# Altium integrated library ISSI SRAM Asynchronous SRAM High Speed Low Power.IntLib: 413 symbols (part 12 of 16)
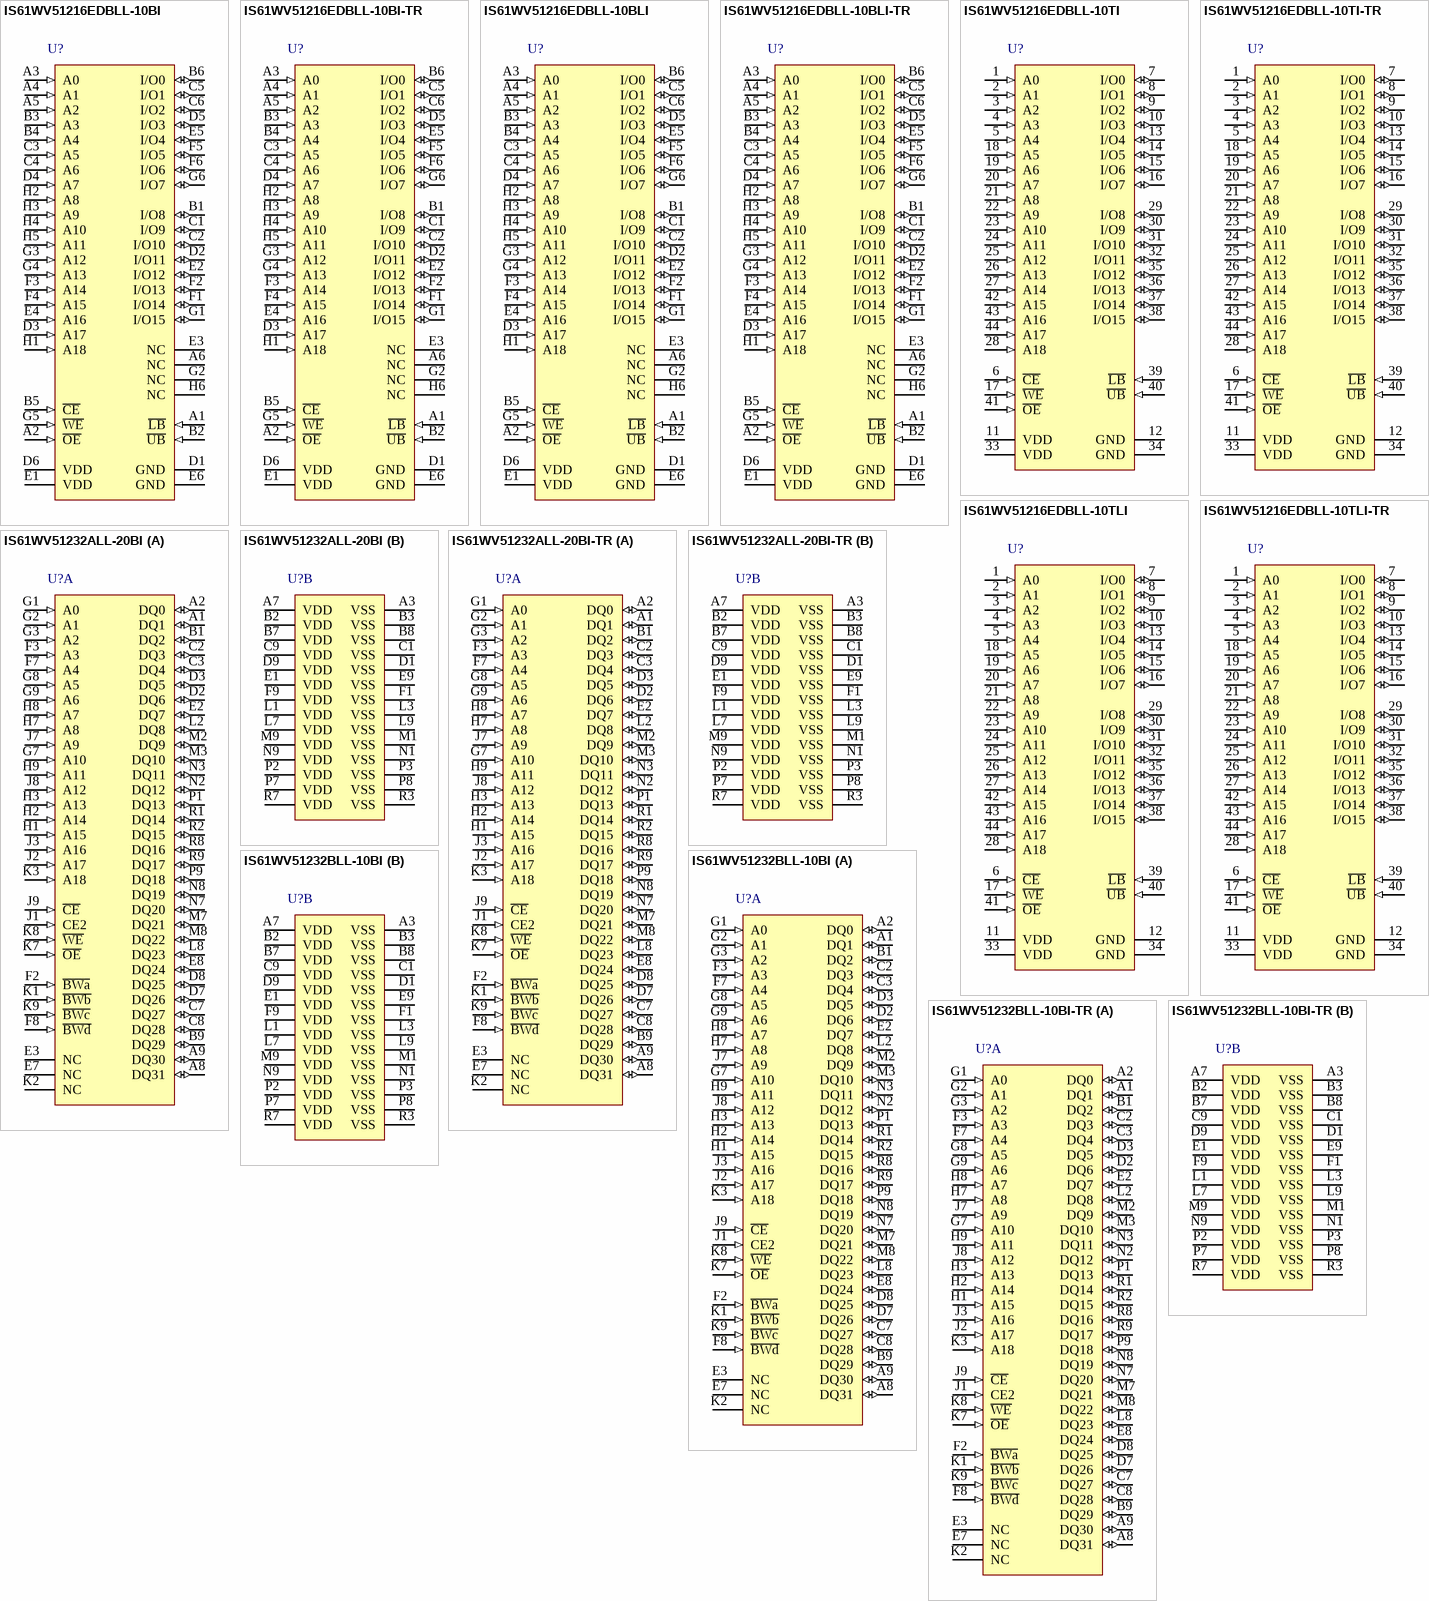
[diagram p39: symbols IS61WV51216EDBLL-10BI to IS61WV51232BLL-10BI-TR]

## IS61WV51232BLL-10BI
designator U?
16 M High Speed Asynchronous CMOS SRAM with 3.3 V Supply, 512 K x 32, -40 to 85 degC, 90-Pin BGA (LF-BGA-90); Manufacturer: Integrated Silicon Solution Inc (ISSI); PartNumber: IS61WV51232BLL-10BI; Density: 16M; Packing: Tray / Tube; Speed (ns): 10
footprint ISSI-TF-BGA-90-8000X13000DE (BGA, 90-Balls, Body 13x8mm, Pitch 0.8mm)
part A pins: A1 DQ1 (io) "Data I/O", A2 DQ0 (io) "Data I/O", A8 DQ31 (io) "Data I/O", A9 DQ30 (io) "Data I/O", B1 DQ2 (io) "Data I/O", B9 DQ29 (io) "Data I/O", C2 DQ3 (io) "Data I/O", C3 DQ4 (io) "Data I/O", C7 DQ27 (io) "Data I/O", C8 DQ28 (io) "Data I/O", D2 DQ6 (io) "Data I/O", D3 DQ5 (io) "Data I/O", D7 DQ26 (io) "Data I/O", D8 DQ25 (io) "Data I/O", E2 DQ7 (io) "Data I/O", E3 NC "No Connection", E7 NC "No Connection", E8 DQ24 (io) "Data I/O", F2 ~{BWa} (in) "Byte Write Control", F3 A3 (in) "Address Inputs", F7 A4 (in) "Address Inputs", F8 ~{BWd} (in) "Byte Write Control", G1 A0 (in) "Address Inputs", G2 A1 (in) "Address Inputs", G3 A2 (in) "Address Inputs", G7 A10 (in) "Address Inputs", G8 A5 (in) "Address Inputs", G9 A6 (in) "Address Inputs", H1 A15 (in) "Address Inputs", H2 A14 (in) "Address Inputs", H3 A13 (in) "Address Inputs", H7 A8 (in) "Address Inputs", H8 A7 (in) "Address Inputs", H9 A11 (in) "Address Inputs", J1 CE2 (in) "Chip Enable Input", J2 A17 (in) "Address Inputs", J3 A16 (in) "Address Inputs", J7 A9 (in) "Address Inputs", J8 A12 (in) "Address Inputs", J9 ~{CE} (in) "Chip Enable Input", K1 ~{BWb} (in) "Byte Write Control", K2 NC "No Connection", K3 A18 (in) "Address Inputs", K7 ~{OE} (in) "Output Enable Input", K8 ~{WE} (in) "Write Enable Input", K9 ~{BWc} (in) "Byte Write Control", L2 DQ8 (io) "Data I/O", L8 DQ23 (io) "Data I/O", M2 DQ9 (io) "Data I/O", M3 DQ10 (io) "Data I/O", M7 DQ21 (io) "Data I/O", M8 DQ22 (io) "Data I/O", N2 DQ12 (io) "Data I/O", N3 DQ11 (io) "Data I/O", N7 DQ20 (io) "Data I/O", N8 DQ19 (io) "Data I/O", P1 DQ13 (io) "Data I/O", P9 DQ18 (io) "Data I/O", R1 DQ14 (io) "Data I/O", R2 DQ15 (io) "Data I/O", R8 DQ16 (io) "Data I/O", R9 DQ17 (io) "Data I/O"
part B pins: A3 VSS (power) "Ground", A7 VDD (power) "Power", B2 VDD (power) "Power", B3 VSS (power) "Ground", B7 VDD (power) "Power", B8 VSS (power) "Ground", C1 VSS (power) "Ground", C9 VDD (power) "Power", D1 VSS (power) "Ground", D9 VDD (power) "Power", E1 VDD (power) "Power", E9 VSS (power) "Ground", F1 VSS (power) "Ground", F9 VDD (power) "Power", L1 VDD (power) "Power", L3 VSS (power) "Ground", L7 VDD (power) "Power", L9 VSS (power) "Ground", M1 VSS (power) "Ground", M9 VDD (power) "Power", N1 VSS (power) "Ground", N9 VDD (power) "Power", P2 VDD (power) "Power", P3 VSS (power) "Ground", P7 VDD (power) "Power", P8 VSS (power) "Ground", R3 VSS (power) "Ground", R7 VDD (power) "Power"

## IS61WV51232BLL-10BI-TR
designator U?
16 M High Speed Asynchronous CMOS SRAM with 3.3 V Supply, 512 K x 32, -40 to 85 degC, 90-Pin BGA (LF-BGA-90); Manufacturer: Integrated Silicon Solution Inc (ISSI); PartNumber: IS61WV51232BLL-10BI-TR; Density: 16M; Packing: Tape & Reel; Speed (ns): 10
footprint ISSI-TF-BGA-90-8000X13000DE (BGA, 90-Balls, Body 13x8mm, Pitch 0.8mm)
part A pins: A1 DQ1 (io) "Data I/O", A2 DQ0 (io) "Data I/O", A8 DQ31 (io) "Data I/O", A9 DQ30 (io) "Data I/O", B1 DQ2 (io) "Data I/O", B9 DQ29 (io) "Data I/O", C2 DQ3 (io) "Data I/O", C3 DQ4 (io) "Data I/O", C7 DQ27 (io) "Data I/O", C8 DQ28 (io) "Data I/O", D2 DQ6 (io) "Data I/O", D3 DQ5 (io) "Data I/O", D7 DQ26 (io) "Data I/O", D8 DQ25 (io) "Data I/O", E2 DQ7 (io) "Data I/O", E3 NC "No Connection", E7 NC "No Connection", E8 DQ24 (io) "Data I/O", F2 ~{BWa} (in) "Byte Write Control", F3 A3 (in) "Address Inputs", F7 A4 (in) "Address Inputs", F8 ~{BWd} (in) "Byte Write Control", G1 A0 (in) "Address Inputs", G2 A1 (in) "Address Inputs", G3 A2 (in) "Address Inputs", G7 A10 (in) "Address Inputs", G8 A5 (in) "Address Inputs", G9 A6 (in) "Address Inputs", H1 A15 (in) "Address Inputs", H2 A14 (in) "Address Inputs", H3 A13 (in) "Address Inputs", H7 A8 (in) "Address Inputs", H8 A7 (in) "Address Inputs", H9 A11 (in) "Address Inputs", J1 CE2 (in) "Chip Enable Input", J2 A17 (in) "Address Inputs", J3 A16 (in) "Address Inputs", J7 A9 (in) "Address Inputs", J8 A12 (in) "Address Inputs", J9 ~{CE} (in) "Chip Enable Input", K1 ~{BWb} (in) "Byte Write Control", K2 NC "No Connection", K3 A18 (in) "Address Inputs", K7 ~{OE} (in) "Output Enable Input", K8 ~{WE} (in) "Write Enable Input", K9 ~{BWc} (in) "Byte Write Control", L2 DQ8 (io) "Data I/O", L8 DQ23 (io) "Data I/O", M2 DQ9 (io) "Data I/O", M3 DQ10 (io) "Data I/O", M7 DQ21 (io) "Data I/O", M8 DQ22 (io) "Data I/O", N2 DQ12 (io) "Data I/O", N3 DQ11 (io) "Data I/O", N7 DQ20 (io) "Data I/O", N8 DQ19 (io) "Data I/O", P1 DQ13 (io) "Data I/O", P9 DQ18 (io) "Data I/O", R1 DQ14 (io) "Data I/O", R2 DQ15 (io) "Data I/O", R8 DQ16 (io) "Data I/O", R9 DQ17 (io) "Data I/O"
part B pins: A3 VSS (power) "Ground", A7 VDD (power) "Power", B2 VDD (power) "Power", B3 VSS (power) "Ground", B7 VDD (power) "Power", B8 VSS (power) "Ground", C1 VSS (power) "Ground", C9 VDD (power) "Power", D1 VSS (power) "Ground", D9 VDD (power) "Power", E1 VDD (power) "Power", E9 VSS (power) "Ground", F1 VSS (power) "Ground", F9 VDD (power) "Power", L1 VDD (power) "Power", L3 VSS (power) "Ground", L7 VDD (power) "Power", L9 VSS (power) "Ground", M1 VSS (power) "Ground", M9 VDD (power) "Power", N1 VSS (power) "Ground", N9 VDD (power) "Power", P2 VDD (power) "Power", P3 VSS (power) "Ground", P7 VDD (power) "Power", P8 VSS (power) "Ground", R3 VSS (power) "Ground", R7 VDD (power) "Power"

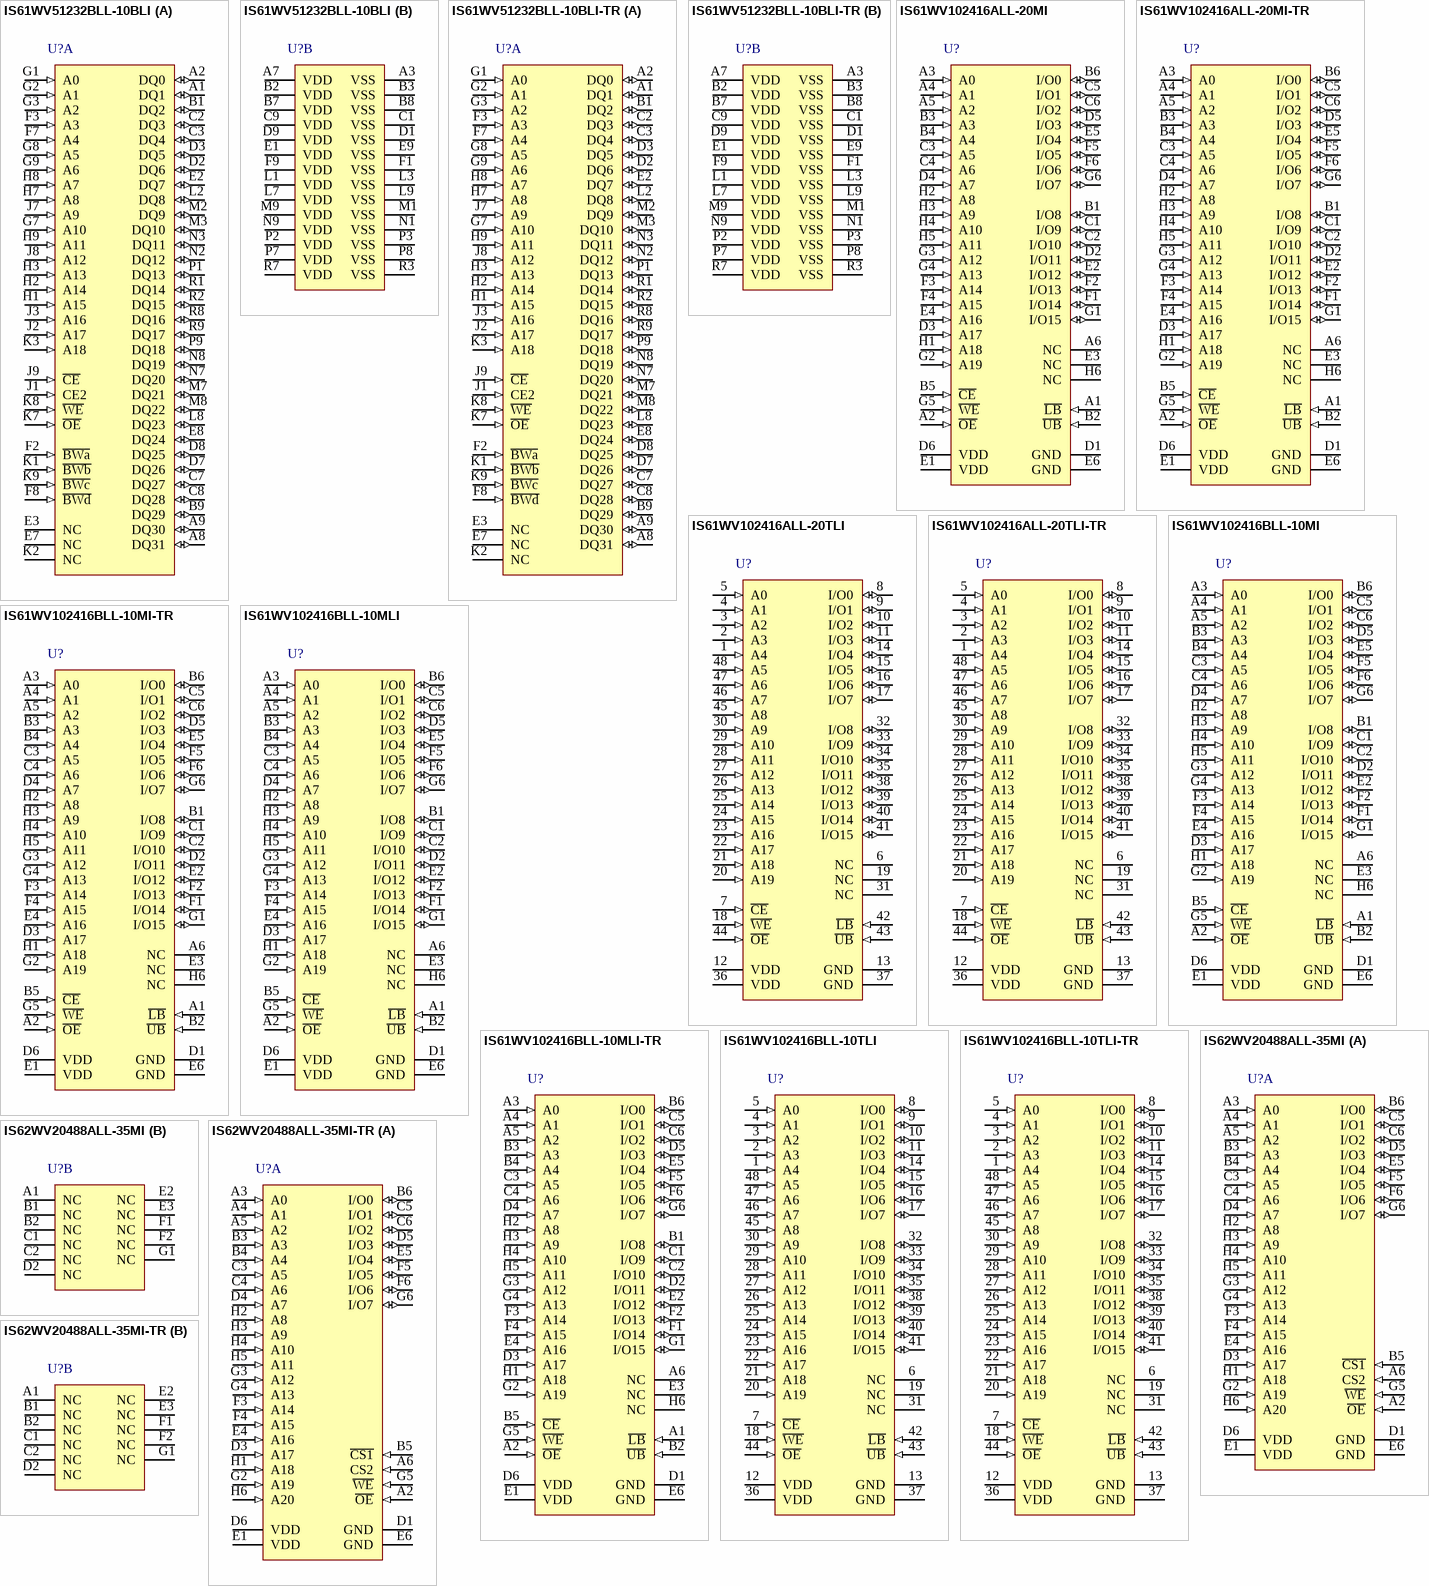
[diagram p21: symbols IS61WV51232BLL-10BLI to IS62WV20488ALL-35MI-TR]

## IS61WV51232BLL-10BLI
designator U?
16 M High Speed Asynchronous CMOS SRAM with 3.3 V Supply, 512 K x 32, -40 to 85 degC, 90-Pin BGA (LF-BGA-90), Pb-Free; Manufacturer: Integrated Silicon Solution Inc (ISSI); PartNumber: IS61WV51232BLL-10BLI; Density: 16M; Packing: Tray / Tube; Speed (ns): 10
footprint ISSI-TF-BGA-90-8000X13000DE (BGA, 90-Balls, Body 13x8mm, Pitch 0.8mm)
part A pins: A1 DQ1 (io) "Data I/O", A2 DQ0 (io) "Data I/O", A8 DQ31 (io) "Data I/O", A9 DQ30 (io) "Data I/O", B1 DQ2 (io) "Data I/O", B9 DQ29 (io) "Data I/O", C2 DQ3 (io) "Data I/O", C3 DQ4 (io) "Data I/O", C7 DQ27 (io) "Data I/O", C8 DQ28 (io) "Data I/O", D2 DQ6 (io) "Data I/O", D3 DQ5 (io) "Data I/O", D7 DQ26 (io) "Data I/O", D8 DQ25 (io) "Data I/O", E2 DQ7 (io) "Data I/O", E3 NC "No Connection", E7 NC "No Connection", E8 DQ24 (io) "Data I/O", F2 ~{BWa} (in) "Byte Write Control", F3 A3 (in) "Address Inputs", F7 A4 (in) "Address Inputs", F8 ~{BWd} (in) "Byte Write Control", G1 A0 (in) "Address Inputs", G2 A1 (in) "Address Inputs", G3 A2 (in) "Address Inputs", G7 A10 (in) "Address Inputs", G8 A5 (in) "Address Inputs", G9 A6 (in) "Address Inputs", H1 A15 (in) "Address Inputs", H2 A14 (in) "Address Inputs", H3 A13 (in) "Address Inputs", H7 A8 (in) "Address Inputs", H8 A7 (in) "Address Inputs", H9 A11 (in) "Address Inputs", J1 CE2 (in) "Chip Enable Input", J2 A17 (in) "Address Inputs", J3 A16 (in) "Address Inputs", J7 A9 (in) "Address Inputs", J8 A12 (in) "Address Inputs", J9 ~{CE} (in) "Chip Enable Input", K1 ~{BWb} (in) "Byte Write Control", K2 NC "No Connection", K3 A18 (in) "Address Inputs", K7 ~{OE} (in) "Output Enable Input", K8 ~{WE} (in) "Write Enable Input", K9 ~{BWc} (in) "Byte Write Control", L2 DQ8 (io) "Data I/O", L8 DQ23 (io) "Data I/O", M2 DQ9 (io) "Data I/O", M3 DQ10 (io) "Data I/O", M7 DQ21 (io) "Data I/O", M8 DQ22 (io) "Data I/O", N2 DQ12 (io) "Data I/O", N3 DQ11 (io) "Data I/O", N7 DQ20 (io) "Data I/O", N8 DQ19 (io) "Data I/O", P1 DQ13 (io) "Data I/O", P9 DQ18 (io) "Data I/O", R1 DQ14 (io) "Data I/O", R2 DQ15 (io) "Data I/O", R8 DQ16 (io) "Data I/O", R9 DQ17 (io) "Data I/O"
part B pins: A3 VSS (power) "Ground", A7 VDD (power) "Power", B2 VDD (power) "Power", B3 VSS (power) "Ground", B7 VDD (power) "Power", B8 VSS (power) "Ground", C1 VSS (power) "Ground", C9 VDD (power) "Power", D1 VSS (power) "Ground", D9 VDD (power) "Power", E1 VDD (power) "Power", E9 VSS (power) "Ground", F1 VSS (power) "Ground", F9 VDD (power) "Power", L1 VDD (power) "Power", L3 VSS (power) "Ground", L7 VDD (power) "Power", L9 VSS (power) "Ground", M1 VSS (power) "Ground", M9 VDD (power) "Power", N1 VSS (power) "Ground", N9 VDD (power) "Power", P2 VDD (power) "Power", P3 VSS (power) "Ground", P7 VDD (power) "Power", P8 VSS (power) "Ground", R3 VSS (power) "Ground", R7 VDD (power) "Power"

## IS61WV51232BLL-10BLI-TR
designator U?
16 M High Speed Asynchronous CMOS SRAM with 3.3 V Supply, 512 K x 32, -40 to 85 degC, 90-Pin BGA (LF-BGA-90), Pb-Free; Manufacturer: Integrated Silicon Solution Inc (ISSI); PartNumber: IS61WV51232BLL-10BLI-TR; Density: 16M; Packing: Tape & Reel; Speed (ns): 10
footprint ISSI-LF-BGA-90-8000X13000DE (BGA, 90-Balls, Body 13x8mm, Pitch 0.8mm)
part A pins: A1 DQ1 (io) "Data I/O", A2 DQ0 (io) "Data I/O", A8 DQ31 (io) "Data I/O", A9 DQ30 (io) "Data I/O", B1 DQ2 (io) "Data I/O", B9 DQ29 (io) "Data I/O", C2 DQ3 (io) "Data I/O", C3 DQ4 (io) "Data I/O", C7 DQ27 (io) "Data I/O", C8 DQ28 (io) "Data I/O", D2 DQ6 (io) "Data I/O", D3 DQ5 (io) "Data I/O", D7 DQ26 (io) "Data I/O", D8 DQ25 (io) "Data I/O", E2 DQ7 (io) "Data I/O", E3 NC "No Connection", E7 NC "No Connection", E8 DQ24 (io) "Data I/O", F2 ~{BWa} (in) "Byte Write Control", F3 A3 (in) "Address Inputs", F7 A4 (in) "Address Inputs", F8 ~{BWd} (in) "Byte Write Control", G1 A0 (in) "Address Inputs", G2 A1 (in) "Address Inputs", G3 A2 (in) "Address Inputs", G7 A10 (in) "Address Inputs", G8 A5 (in) "Address Inputs", G9 A6 (in) "Address Inputs", H1 A15 (in) "Address Inputs", H2 A14 (in) "Address Inputs", H3 A13 (in) "Address Inputs", H7 A8 (in) "Address Inputs", H8 A7 (in) "Address Inputs", H9 A11 (in) "Address Inputs", J1 CE2 (in) "Chip Enable Input", J2 A17 (in) "Address Inputs", J3 A16 (in) "Address Inputs", J7 A9 (in) "Address Inputs", J8 A12 (in) "Address Inputs", J9 ~{CE} (in) "Chip Enable Input", K1 ~{BWb} (in) "Byte Write Control", K2 NC "No Connection", K3 A18 (in) "Address Inputs", K7 ~{OE} (in) "Output Enable Input", K8 ~{WE} (in) "Write Enable Input", K9 ~{BWc} (in) "Byte Write Control", L2 DQ8 (io) "Data I/O", L8 DQ23 (io) "Data I/O", M2 DQ9 (io) "Data I/O", M3 DQ10 (io) "Data I/O", M7 DQ21 (io) "Data I/O", M8 DQ22 (io) "Data I/O", N2 DQ12 (io) "Data I/O", N3 DQ11 (io) "Data I/O", N7 DQ20 (io) "Data I/O", N8 DQ19 (io) "Data I/O", P1 DQ13 (io) "Data I/O", P9 DQ18 (io) "Data I/O", R1 DQ14 (io) "Data I/O", R2 DQ15 (io) "Data I/O", R8 DQ16 (io) "Data I/O", R9 DQ17 (io) "Data I/O"
part B pins: A3 VSS (power) "Ground", A7 VDD (power) "Power", B2 VDD (power) "Power", B3 VSS (power) "Ground", B7 VDD (power) "Power", B8 VSS (power) "Ground", C1 VSS (power) "Ground", C9 VDD (power) "Power", D1 VSS (power) "Ground", D9 VDD (power) "Power", E1 VDD (power) "Power", E9 VSS (power) "Ground", F1 VSS (power) "Ground", F9 VDD (power) "Power", L1 VDD (power) "Power", L3 VSS (power) "Ground", L7 VDD (power) "Power", L9 VSS (power) "Ground", M1 VSS (power) "Ground", M9 VDD (power) "Power", N1 VSS (power) "Ground", N9 VDD (power) "Power", P2 VDD (power) "Power", P3 VSS (power) "Ground", P7 VDD (power) "Power", P8 VSS (power) "Ground", R3 VSS (power) "Ground", R7 VDD (power) "Power"

## IS61WV102416ALL-20MI
designator U?
16 M High Speed Asynchronous CMOS SRAM with 3.3 V Supply, 1 M x 16, -40 to 85 degC, 48-Pin BGA (TF-BGA-48); Manufacturer: Integrated Silicon Solution Inc (ISSI); PartNumber: IS61WV102416ALL-20MI; Density: 16M; Organization: 1M x 16; Packing: Tray / Tube; Speed (ns): 20
footprint ISSI-TF-BGA-48-9000x11000DE (BGA, 48-Balls, Body 11x9mm, Pitch 0.75mm)
pins: A1 ~{LB} (in) "Lower-byte Control (I/O0-I/O7)", A2 ~{OE} (in) "Output Enable Input", A3 A0 (in) "Address Input", A4 A1 (in) "Address Input", A5 A2 (in) "Address Input", A6 NC "No Connection", B1 I/O8 (io) "Data Inputs/Output", B2 ~{UB} (in) "Upper-byte Control (I/O8-I/O15)", B3 A3 (in) "Address Input", B4 A4 (in) "Address Input", B5 ~{CE} (in) "Chip Enable Input", B6 I/O0 (io) "Data Inputs/Output", C1 I/O9 (io) "Data Inputs/Output", C2 I/O10 (io) "Data Inputs/Output", C3 A5 (in) "Address Input", C4 A6 (in) "Address Input", C5 I/O1 (io) "Data Inputs/Output", C6 I/O2 (io) "Data Inputs/Output", D1 GND (power) "Ground", D2 I/O11 (io) "Data Inputs/Output", D3 A17 (in) "Address Input", D4 A7 (in) "Address Input", D5 I/O3 (io) "Data Inputs/Output", D6 VDD (power) "Power", E1 VDD (power) "Power", E2 I/O12 (io) "Data Inputs/Output", E3 NC "No Connection", E4 A16 (in) "Address Input", E5 I/O4 (io) "Data Inputs/Output", E6 GND (power) "Ground", F1 I/O14 (io) "Data Inputs/Output", F2 I/O13 (io) "Data Inputs/Output", F3 A14 (in) "Address Input", F4 A15 (in) "Address Input", F5 I/O5 (io) "Data Inputs/Output", F6 I/O6 (io) "Data Inputs/Output", G1 I/O15 (io) "Data Inputs/Output", G2 A19 (in) "Address Input", G3 A12 (in) "Address Input", G4 A13 (in) "Address Input", G5 ~{WE} (in) "Write Enable Input", G6 I/O7 (io) "Data Inputs/Output", H1 A18 (in) "Address Input", H2 A8 (in) "Address Input", H3 A9 (in) "Address Input", H4 A10 (in) "Address Input", H5 A11 (in) "Address Input", H6 NC "No Connection"

## IS61WV102416ALL-20MI-TR
designator U?
16 M High Speed Asynchronous CMOS SRAM with 3.3 V Supply, 1 M x 16, -40 to 85 degC, 48-Pin BGA (TF-BGA-48); Manufacturer: Integrated Silicon Solution Inc (ISSI); PartNumber: IS61WV102416ALL-20MI-TR; Density: 16M; Organization: 1M x 16; Packing: Tape & Reel; Speed (ns): 20
footprint ISSI-TF-BGA-48-9000x11000DE (BGA, 48-Balls, Body 11x9mm, Pitch 0.75mm)
pins: A1 ~{LB} (in) "Lower-byte Control (I/O0-I/O7)", A2 ~{OE} (in) "Output Enable Input", A3 A0 (in) "Address Input", A4 A1 (in) "Address Input", A5 A2 (in) "Address Input", A6 NC "No Connection", B1 I/O8 (io) "Data Inputs/Output", B2 ~{UB} (in) "Upper-byte Control (I/O8-I/O15)", B3 A3 (in) "Address Input", B4 A4 (in) "Address Input", B5 ~{CE} (in) "Chip Enable Input", B6 I/O0 (io) "Data Inputs/Output", C1 I/O9 (io) "Data Inputs/Output", C2 I/O10 (io) "Data Inputs/Output", C3 A5 (in) "Address Input", C4 A6 (in) "Address Input", C5 I/O1 (io) "Data Inputs/Output", C6 I/O2 (io) "Data Inputs/Output", D1 GND (power) "Ground", D2 I/O11 (io) "Data Inputs/Output", D3 A17 (in) "Address Input", D4 A7 (in) "Address Input", D5 I/O3 (io) "Data Inputs/Output", D6 VDD (power) "Power", E1 VDD (power) "Power", E2 I/O12 (io) "Data Inputs/Output", E3 NC "No Connection", E4 A16 (in) "Address Input", E5 I/O4 (io) "Data Inputs/Output", E6 GND (power) "Ground", F1 I/O14 (io) "Data Inputs/Output", F2 I/O13 (io) "Data Inputs/Output", F3 A14 (in) "Address Input", F4 A15 (in) "Address Input", F5 I/O5 (io) "Data Inputs/Output", F6 I/O6 (io) "Data Inputs/Output", G1 I/O15 (io) "Data Inputs/Output", G2 A19 (in) "Address Input", G3 A12 (in) "Address Input", G4 A13 (in) "Address Input", G5 ~{WE} (in) "Write Enable Input", G6 I/O7 (io) "Data Inputs/Output", H1 A18 (in) "Address Input", H2 A8 (in) "Address Input", H3 A9 (in) "Address Input", H4 A10 (in) "Address Input", H5 A11 (in) "Address Input", H6 NC "No Connection"

## IS61WV102416ALL-20TLI
designator U?
16 M High Speed Asynchronous CMOS SRAM with 3.3 V Supply, 1 M x 16, -40 to 85 degC, 48-Pin SOP (TSOP-1-48), Pb-Free; Manufacturer: Integrated Silicon Solution Inc (ISSI); PartNumber: IS61WV102416ALL-20TLI; Density: 16M; Organization: 1M x 16; Packing: Tray / Tube; Speed (ns): 20
footprint ISSI-TSOP-1-48-12000X20000DE_N (SOP, 48-Leads, Body 18.6x12.2mm, Pitch 0.5mm, IPC Medium Density)
pins: 1 A4 (in) "Address Input", 2 A3 (in) "Address Input", 3 A2 (in) "Address Input", 4 A1 (in) "Address Input", 5 A0 (in) "Address Input", 6 NC "No Connection", 7 ~{CE} (in) "Chip Enable Input", 8 I/O0 (io) "Data Input/Output", 9 I/O1 (io) "Data Input/Output", 10 I/O2 (io) "Data Input/Output", 11 I/O3 (io) "Data Input/Output", 12 VDD (power) "Power", 13 GND (power) "Ground", 14 I/O4 (io) "Data Input/Output", 15 I/O5 (io) "Data Input/Output", 16 I/O6 (io) "Data Input/Output", 17 I/O7 (io) "Data Input/Output", 18 ~{WE} (in) "Write Enable Input", 19 NC "No Connection", 20 A19 (in) "Address Input", 21 A18 (in) "Address Input", 22 A17 (in) "Address Input", 23 A16 (in) "Address Input", 24 A15 (in) "Address Input", 25 A14 (in) "Address Input", 26 A13 (in) "Address Input", 27 A12 (in) "Address Input", 28 A11 (in) "Address Input", 29 A10 (in) "Address Input", 30 A9 (in) "Address Input", 31 NC "No Connection", 32 I/O8 (io) "Data Input/Output", 33 I/O9 (io) "Data Input/Output", 34 I/O10 (io) "Data Input/Output", 35 I/O11 (io) "Data Input/Output", 36 VDD (power) "Power", 37 GND (power) "Ground", 38 I/O12 (io) "Data Input/Output", 39 I/O13 (io) "Data Input/Output", 40 I/O14 (io) "Data Input/Output", 41 I/O15 (io) "Data Input/Output", 42 ~{LB} (in) "Lower-byte Control (I/O0-I/O7)", 43 ~{UB} (in) "Upper-byte Control (I/O8-I/O15)", 44 ~{OE} (in) "Output Enable Input", 45 A8 (in) "Address Input", 46 A7 (in) "Address Input", 47 A6 (in) "Address Input", 48 A5 (in) "Address Input"

## IS61WV102416ALL-20TLI-TR
designator U?
16 M High Speed Asynchronous CMOS SRAM with 3.3 V Supply, 1 M x 16, -40 to 85 degC, 48-Pin SOP (TSOP-1-48), Pb-Free; Manufacturer: Integrated Silicon Solution Inc (ISSI); PartNumber: IS61WV102416ALL-20TLI-TR; Density: 16M; Organization: 1M x 16; Packing: Tape & Reel; Speed (ns): 20
footprint ISSI-TSOP-1-48-12000X20000DE_N (SOP, 48-Leads, Body 18.6x12.2mm, Pitch 0.5mm, IPC Medium Density)
pins: 1 A4 (in) "Address Input", 2 A3 (in) "Address Input", 3 A2 (in) "Address Input", 4 A1 (in) "Address Input", 5 A0 (in) "Address Input", 6 NC "No Connection", 7 ~{CE} (in) "Chip Enable Input", 8 I/O0 (io) "Data Input/Output", 9 I/O1 (io) "Data Input/Output", 10 I/O2 (io) "Data Input/Output", 11 I/O3 (io) "Data Input/Output", 12 VDD (power) "Power", 13 GND (power) "Ground", 14 I/O4 (io) "Data Input/Output", 15 I/O5 (io) "Data Input/Output", 16 I/O6 (io) "Data Input/Output", 17 I/O7 (io) "Data Input/Output", 18 ~{WE} (in) "Write Enable Input", 19 NC "No Connection", 20 A19 (in) "Address Input", 21 A18 (in) "Address Input", 22 A17 (in) "Address Input", 23 A16 (in) "Address Input", 24 A15 (in) "Address Input", 25 A14 (in) "Address Input", 26 A13 (in) "Address Input", 27 A12 (in) "Address Input", 28 A11 (in) "Address Input", 29 A10 (in) "Address Input", 30 A9 (in) "Address Input", 31 NC "No Connection", 32 I/O8 (io) "Data Input/Output", 33 I/O9 (io) "Data Input/Output", 34 I/O10 (io) "Data Input/Output", 35 I/O11 (io) "Data Input/Output", 36 VDD (power) "Power", 37 GND (power) "Ground", 38 I/O12 (io) "Data Input/Output", 39 I/O13 (io) "Data Input/Output", 40 I/O14 (io) "Data Input/Output", 41 I/O15 (io) "Data Input/Output", 42 ~{LB} (in) "Lower-byte Control (I/O0-I/O7)", 43 ~{UB} (in) "Upper-byte Control (I/O8-I/O15)", 44 ~{OE} (in) "Output Enable Input", 45 A8 (in) "Address Input", 46 A7 (in) "Address Input", 47 A6 (in) "Address Input", 48 A5 (in) "Address Input"

## IS61WV102416BLL-10MI
designator U?
16 M High Speed Asynchronous CMOS SRAM with 3.3 V Supply, 1 M x 16, -40 to 85 degC, 48-Pin BGA (TF-BGA-48); Manufacturer: Integrated Silicon Solution Inc (ISSI); PartNumber: IS61WV102416BLL-10MI; Density: 16M; Organization: 1M x 16; Packing: Tray / Tube; Speed (ns): 10
footprint ISSI-TF-BGA-48-9000x11000DE (BGA, 48-Balls, Body 11x9mm, Pitch 0.75mm)
pins: A1 ~{LB} (in) "Lower-byte Control (I/O0-I/O7)", A2 ~{OE} (in) "Output Enable Input", A3 A0 (in) "Address Input", A4 A1 (in) "Address Input", A5 A2 (in) "Address Input", A6 NC "No Connection", B1 I/O8 (io) "Data Inputs/Output", B2 ~{UB} (in) "Upper-byte Control (I/O8-I/O15)", B3 A3 (in) "Address Input", B4 A4 (in) "Address Input", B5 ~{CE} (in) "Chip Enable Input", B6 I/O0 (io) "Data Inputs/Output", C1 I/O9 (io) "Data Inputs/Output", C2 I/O10 (io) "Data Inputs/Output", C3 A5 (in) "Address Input", C4 A6 (in) "Address Input", C5 I/O1 (io) "Data Inputs/Output", C6 I/O2 (io) "Data Inputs/Output", D1 GND (power) "Ground", D2 I/O11 (io) "Data Inputs/Output", D3 A17 (in) "Address Input", D4 A7 (in) "Address Input", D5 I/O3 (io) "Data Inputs/Output", D6 VDD (power) "Power", E1 VDD (power) "Power", E2 I/O12 (io) "Data Inputs/Output", E3 NC "No Connection", E4 A16 (in) "Address Input", E5 I/O4 (io) "Data Inputs/Output", E6 GND (power) "Ground", F1 I/O14 (io) "Data Inputs/Output", F2 I/O13 (io) "Data Inputs/Output", F3 A14 (in) "Address Input", F4 A15 (in) "Address Input", F5 I/O5 (io) "Data Inputs/Output", F6 I/O6 (io) "Data Inputs/Output", G1 I/O15 (io) "Data Inputs/Output", G2 A19 (in) "Address Input", G3 A12 (in) "Address Input", G4 A13 (in) "Address Input", G5 ~{WE} (in) "Write Enable Input", G6 I/O7 (io) "Data Inputs/Output", H1 A18 (in) "Address Input", H2 A8 (in) "Address Input", H3 A9 (in) "Address Input", H4 A10 (in) "Address Input", H5 A11 (in) "Address Input", H6 NC "No Connection"

## IS61WV102416BLL-10MI-TR
designator U?
16 M High Speed Asynchronous CMOS SRAM with 3.3 V Supply, 1 M x 16, -40 to 85 degC, 48-Pin BGA (TF-BGA-48); Manufacturer: Integrated Silicon Solution Inc (ISSI); PartNumber: IS61WV102416BLL-10MI-TR; Density: 16M; Organization: 1M x 16; Packing: Tape & Reel; Speed (ns): 10
footprint ISSI-TF-BGA-48-9000x11000DE (BGA, 48-Balls, Body 11x9mm, Pitch 0.75mm)
pins: A1 ~{LB} (in) "Lower-byte Control (I/O0-I/O7)", A2 ~{OE} (in) "Output Enable Input", A3 A0 (in) "Address Input", A4 A1 (in) "Address Input", A5 A2 (in) "Address Input", A6 NC "No Connection", B1 I/O8 (io) "Data Inputs/Output", B2 ~{UB} (in) "Upper-byte Control (I/O8-I/O15)", B3 A3 (in) "Address Input", B4 A4 (in) "Address Input", B5 ~{CE} (in) "Chip Enable Input", B6 I/O0 (io) "Data Inputs/Output", C1 I/O9 (io) "Data Inputs/Output", C2 I/O10 (io) "Data Inputs/Output", C3 A5 (in) "Address Input", C4 A6 (in) "Address Input", C5 I/O1 (io) "Data Inputs/Output", C6 I/O2 (io) "Data Inputs/Output", D1 GND (power) "Ground", D2 I/O11 (io) "Data Inputs/Output", D3 A17 (in) "Address Input", D4 A7 (in) "Address Input", D5 I/O3 (io) "Data Inputs/Output", D6 VDD (power) "Power", E1 VDD (power) "Power", E2 I/O12 (io) "Data Inputs/Output", E3 NC "No Connection", E4 A16 (in) "Address Input", E5 I/O4 (io) "Data Inputs/Output", E6 GND (power) "Ground", F1 I/O14 (io) "Data Inputs/Output", F2 I/O13 (io) "Data Inputs/Output", F3 A14 (in) "Address Input", F4 A15 (in) "Address Input", F5 I/O5 (io) "Data Inputs/Output", F6 I/O6 (io) "Data Inputs/Output", G1 I/O15 (io) "Data Inputs/Output", G2 A19 (in) "Address Input", G3 A12 (in) "Address Input", G4 A13 (in) "Address Input", G5 ~{WE} (in) "Write Enable Input", G6 I/O7 (io) "Data Inputs/Output", H1 A18 (in) "Address Input", H2 A8 (in) "Address Input", H3 A9 (in) "Address Input", H4 A10 (in) "Address Input", H5 A11 (in) "Address Input", H6 NC "No Connection"

## IS61WV102416BLL-10MLI
designator U?
16 M High Speed Asynchronous CMOS SRAM with 3.3 V Supply, 1 M x 16, -40 to 85 degC, 48-Pin BGA (TF-BGA-48), Pb-Free; Manufacturer: Integrated Silicon Solution Inc (ISSI); PartNumber: IS61WV102416BLL-10MLI; Density: 16M; Organization: 1M x 16; Packing: Tray / Tube; Speed (ns): 10
footprint ISSI-TF-BGA-48-9000x11000DE (BGA, 48-Balls, Body 11x9mm, Pitch 0.75mm)
pins: A1 ~{LB} (in) "Lower-byte Control (I/O0-I/O7)", A2 ~{OE} (in) "Output Enable Input", A3 A0 (in) "Address Input", A4 A1 (in) "Address Input", A5 A2 (in) "Address Input", A6 NC "No Connection", B1 I/O8 (io) "Data Inputs/Output", B2 ~{UB} (in) "Upper-byte Control (I/O8-I/O15)", B3 A3 (in) "Address Input", B4 A4 (in) "Address Input", B5 ~{CE} (in) "Chip Enable Input", B6 I/O0 (io) "Data Inputs/Output", C1 I/O9 (io) "Data Inputs/Output", C2 I/O10 (io) "Data Inputs/Output", C3 A5 (in) "Address Input", C4 A6 (in) "Address Input", C5 I/O1 (io) "Data Inputs/Output", C6 I/O2 (io) "Data Inputs/Output", D1 GND (power) "Ground", D2 I/O11 (io) "Data Inputs/Output", D3 A17 (in) "Address Input", D4 A7 (in) "Address Input", D5 I/O3 (io) "Data Inputs/Output", D6 VDD (power) "Power", E1 VDD (power) "Power", E2 I/O12 (io) "Data Inputs/Output", E3 NC "No Connection", E4 A16 (in) "Address Input", E5 I/O4 (io) "Data Inputs/Output", E6 GND (power) "Ground", F1 I/O14 (io) "Data Inputs/Output", F2 I/O13 (io) "Data Inputs/Output", F3 A14 (in) "Address Input", F4 A15 (in) "Address Input", F5 I/O5 (io) "Data Inputs/Output", F6 I/O6 (io) "Data Inputs/Output", G1 I/O15 (io) "Data Inputs/Output", G2 A19 (in) "Address Input", G3 A12 (in) "Address Input", G4 A13 (in) "Address Input", G5 ~{WE} (in) "Write Enable Input", G6 I/O7 (io) "Data Inputs/Output", H1 A18 (in) "Address Input", H2 A8 (in) "Address Input", H3 A9 (in) "Address Input", H4 A10 (in) "Address Input", H5 A11 (in) "Address Input", H6 NC "No Connection"

## IS61WV102416BLL-10MLI-TR
designator U?
16 M High Speed Asynchronous CMOS SRAM with 3.3 V Supply, 1 M x 16, -40 to 85 degC, 48-Pin BGA (TF-BGA-48), Pb-Free; Manufacturer: Integrated Silicon Solution Inc (ISSI); PartNumber: IS61WV102416BLL-10MLI-TR; Density: 16M; Organization: 1M x 16; Packing: Tape & Reel; Speed (ns): 10
footprint ISSI-TF-BGA-48-9000x11000DE (BGA, 48-Balls, Body 11x9mm, Pitch 0.75mm)
pins: A1 ~{LB} (in) "Lower-byte Control (I/O0-I/O7)", A2 ~{OE} (in) "Output Enable Input", A3 A0 (in) "Address Input", A4 A1 (in) "Address Input", A5 A2 (in) "Address Input", A6 NC "No Connection", B1 I/O8 (io) "Data Inputs/Output", B2 ~{UB} (in) "Upper-byte Control (I/O8-I/O15)", B3 A3 (in) "Address Input", B4 A4 (in) "Address Input", B5 ~{CE} (in) "Chip Enable Input", B6 I/O0 (io) "Data Inputs/Output", C1 I/O9 (io) "Data Inputs/Output", C2 I/O10 (io) "Data Inputs/Output", C3 A5 (in) "Address Input", C4 A6 (in) "Address Input", C5 I/O1 (io) "Data Inputs/Output", C6 I/O2 (io) "Data Inputs/Output", D1 GND (power) "Ground", D2 I/O11 (io) "Data Inputs/Output", D3 A17 (in) "Address Input", D4 A7 (in) "Address Input", D5 I/O3 (io) "Data Inputs/Output", D6 VDD (power) "Power", E1 VDD (power) "Power", E2 I/O12 (io) "Data Inputs/Output", E3 NC "No Connection", E4 A16 (in) "Address Input", E5 I/O4 (io) "Data Inputs/Output", E6 GND (power) "Ground", F1 I/O14 (io) "Data Inputs/Output", F2 I/O13 (io) "Data Inputs/Output", F3 A14 (in) "Address Input", F4 A15 (in) "Address Input", F5 I/O5 (io) "Data Inputs/Output", F6 I/O6 (io) "Data Inputs/Output", G1 I/O15 (io) "Data Inputs/Output", G2 A19 (in) "Address Input", G3 A12 (in) "Address Input", G4 A13 (in) "Address Input", G5 ~{WE} (in) "Write Enable Input", G6 I/O7 (io) "Data Inputs/Output", H1 A18 (in) "Address Input", H2 A8 (in) "Address Input", H3 A9 (in) "Address Input", H4 A10 (in) "Address Input", H5 A11 (in) "Address Input", H6 NC "No Connection"

## IS61WV102416BLL-10TLI
designator U?
16 M High Speed Asynchronous CMOS SRAM with 3.3 V Supply, 1 M x 16, -40 to 85 degC, 48-Pin SOP (TSOP-1-48), Pb-Free; Manufacturer: Integrated Silicon Solution Inc (ISSI); PartNumber: IS61WV102416BLL-10TLI; Density: 16M; Organization: 1M x 16; Packing: Tray / Tube; Speed (ns): 10
footprint ISSI-TSOP-1-48-12000X20000DE_N (SOP, 48-Leads, Body 18.6x12.2mm, Pitch 0.5mm, IPC Medium Density)
pins: 1 A4 (in) "Address Input", 2 A3 (in) "Address Input", 3 A2 (in) "Address Input", 4 A1 (in) "Address Input", 5 A0 (in) "Address Input", 6 NC "No Connection", 7 ~{CE} (in) "Chip Enable Input", 8 I/O0 (io) "Data Input/Output", 9 I/O1 (io) "Data Input/Output", 10 I/O2 (io) "Data Input/Output", 11 I/O3 (io) "Data Input/Output", 12 VDD (power) "Power", 13 GND (power) "Ground", 14 I/O4 (io) "Data Input/Output", 15 I/O5 (io) "Data Input/Output", 16 I/O6 (io) "Data Input/Output", 17 I/O7 (io) "Data Input/Output", 18 ~{WE} (in) "Write Enable Input", 19 NC "No Connection", 20 A19 (in) "Address Input", 21 A18 (in) "Address Input", 22 A17 (in) "Address Input", 23 A16 (in) "Address Input", 24 A15 (in) "Address Input", 25 A14 (in) "Address Input", 26 A13 (in) "Address Input", 27 A12 (in) "Address Input", 28 A11 (in) "Address Input", 29 A10 (in) "Address Input", 30 A9 (in) "Address Input", 31 NC "No Connection", 32 I/O8 (io) "Data Input/Output", 33 I/O9 (io) "Data Input/Output", 34 I/O10 (io) "Data Input/Output", 35 I/O11 (io) "Data Input/Output", 36 VDD (power) "Power", 37 GND (power) "Ground", 38 I/O12 (io) "Data Input/Output", 39 I/O13 (io) "Data Input/Output", 40 I/O14 (io) "Data Input/Output", 41 I/O15 (io) "Data Input/Output", 42 ~{LB} (in) "Lower-byte Control (I/O0-I/O7)", 43 ~{UB} (in) "Upper-byte Control (I/O8-I/O15)", 44 ~{OE} (in) "Output Enable Input", 45 A8 (in) "Address Input", 46 A7 (in) "Address Input", 47 A6 (in) "Address Input", 48 A5 (in) "Address Input"

## IS61WV102416BLL-10TLI-TR
designator U?
16 M High Speed Asynchronous CMOS SRAM with 3.3 V Supply, 1 M x 16, -40 to 85 degC, 48-Pin SOP (TSOP-1-48), Pb-Free; Manufacturer: Integrated Silicon Solution Inc (ISSI); PartNumber: IS61WV102416BLL-10TLI-TR; Density: 16M; Organization: 1M x 16; Packing: Tape & Reel; Speed (ns): 10
footprint ISSI-TSOP-1-48-12000X20000DE_N (SOP, 48-Leads, Body 18.6x12.2mm, Pitch 0.5mm, IPC Medium Density)
pins: 1 A4 (in) "Address Input", 2 A3 (in) "Address Input", 3 A2 (in) "Address Input", 4 A1 (in) "Address Input", 5 A0 (in) "Address Input", 6 NC "No Connection", 7 ~{CE} (in) "Chip Enable Input", 8 I/O0 (io) "Data Input/Output", 9 I/O1 (io) "Data Input/Output", 10 I/O2 (io) "Data Input/Output", 11 I/O3 (io) "Data Input/Output", 12 VDD (power) "Power", 13 GND (power) "Ground", 14 I/O4 (io) "Data Input/Output", 15 I/O5 (io) "Data Input/Output", 16 I/O6 (io) "Data Input/Output", 17 I/O7 (io) "Data Input/Output", 18 ~{WE} (in) "Write Enable Input", 19 NC "No Connection", 20 A19 (in) "Address Input", 21 A18 (in) "Address Input", 22 A17 (in) "Address Input", 23 A16 (in) "Address Input", 24 A15 (in) "Address Input", 25 A14 (in) "Address Input", 26 A13 (in) "Address Input", 27 A12 (in) "Address Input", 28 A11 (in) "Address Input", 29 A10 (in) "Address Input", 30 A9 (in) "Address Input", 31 NC "No Connection", 32 I/O8 (io) "Data Input/Output", 33 I/O9 (io) "Data Input/Output", 34 I/O10 (io) "Data Input/Output", 35 I/O11 (io) "Data Input/Output", 36 VDD (power) "Power", 37 GND (power) "Ground", 38 I/O12 (io) "Data Input/Output", 39 I/O13 (io) "Data Input/Output", 40 I/O14 (io) "Data Input/Output", 41 I/O15 (io) "Data Input/Output", 42 ~{LB} (in) "Lower-byte Control (I/O0-I/O7)", 43 ~{UB} (in) "Upper-byte Control (I/O8-I/O15)", 44 ~{OE} (in) "Output Enable Input", 45 A8 (in) "Address Input", 46 A7 (in) "Address Input", 47 A6 (in) "Address Input", 48 A5 (in) "Address Input"

## IS62WV20488ALL-35MI
designator U?
16 M High Speed Low Power CMOS SRAM, 2 M x 8, -40 to 85 degC, 48-Pin BGA (TF-BGA-48); Manufacturer: Integrated Silicon Solution Inc (ISSI); PartNumber: IS62WV20488ALL-35MI; Density: 16M; Organization: 2M x 8; Packing: Tray / Tube; Speed (ns): 35
footprint ISSI-TF-BGA-48-9000x11000DE (BGA, 48-Balls, Body 11x9mm, Pitch 0.75mm)
part A pins: A2 ~{OE} (in) "Output Enable Input", A3 A0 (in) "Address Input", A4 A1 (in) "Address Input", A5 A2 (in) "Address Input", A6 CS2 (in) "Chip Enable Input", B3 A3 (in) "Address Input", B4 A4 (in) "Address Input", B5 ~{CS1} (in) "Chip Enable Input", B6 I/O0 (io) "Data Input / Output", C3 A5 (in) "Address Input", C4 A6 (in) "Address Input", C5 I/O1 (io) "Data Input / Output", C6 I/O2 (io) "Data Input / Output", D1 GND (power) "Ground", D3 A17 (in) "Address Input", D4 A7 (in) "Address Input", D5 I/O3 (io) "Data Input / Output", D6 VDD (power) "Power", E1 VDD (power) "Power", E4 A16 (in) "Address Input", E5 I/O4 (io) "Data Input / Output", E6 GND (power) "Ground", F3 A14 (in) "Address Input", F4 A15 (in) "Address Input", F5 I/O5 (io) "Data Input / Output", F6 I/O6 (io) "Data Input / Output", G2 A19 (in) "Address Input", G3 A12 (in) "Address Input", G4 A13 (in) "Address Input", G5 ~{WE} (in) "Write Enable Input", G6 I/O7 (io) "Data Input / Output", H1 A18 (in) "Address Input", H2 A8 (in) "Address Input", H3 A9 (in) "Address Input", H4 A10 (in) "Address Input", H5 A11 (in) "Address Input", H6 A20 (in) "Address Input"
part B pins: A1 NC "No Connection", B1 NC "No Connection", B2 NC "No Connection", C1 NC "No Connection", C2 NC "No Connection", D2 NC "No Connection", E2 NC "No Connection", E3 NC "No Connection", F1 NC "No Connection", F2 NC "No Connection", G1 NC "No Connection"

## IS62WV20488ALL-35MI-TR
designator U?
16 M High Speed Low Power CMOS SRAM, 2 M x 8, -40 to 85 degC, 48-Pin BGA (TF-BGA-48); Manufacturer: Integrated Silicon Solution Inc (ISSI); PartNumber: IS62WV20488ALL-35MI-TR; Density: 16M; Organization: 2M x 8; Packing: Tape & Reel; Speed (ns): 35
footprint ISSI-TF-BGA-48-9000x11000DE (BGA, 48-Balls, Body 11x9mm, Pitch 0.75mm)
part A pins: A2 ~{OE} (in) "Output Enable Input", A3 A0 (in) "Address Input", A4 A1 (in) "Address Input", A5 A2 (in) "Address Input", A6 CS2 (in) "Chip Enable Input", B3 A3 (in) "Address Input", B4 A4 (in) "Address Input", B5 ~{CS1} (in) "Chip Enable Input", B6 I/O0 (io) "Data Input / Output", C3 A5 (in) "Address Input", C4 A6 (in) "Address Input", C5 I/O1 (io) "Data Input / Output", C6 I/O2 (io) "Data Input / Output", D1 GND (power) "Ground", D3 A17 (in) "Address Input", D4 A7 (in) "Address Input", D5 I/O3 (io) "Data Input / Output", D6 VDD (power) "Power", E1 VDD (power) "Power", E4 A16 (in) "Address Input", E5 I/O4 (io) "Data Input / Output", E6 GND (power) "Ground", F3 A14 (in) "Address Input", F4 A15 (in) "Address Input", F5 I/O5 (io) "Data Input / Output", F6 I/O6 (io) "Data Input / Output", G2 A19 (in) "Address Input", G3 A12 (in) "Address Input", G4 A13 (in) "Address Input", G5 ~{WE} (in) "Write Enable Input", G6 I/O7 (io) "Data Input / Output", H1 A18 (in) "Address Input", H2 A8 (in) "Address Input", H3 A9 (in) "Address Input", H4 A10 (in) "Address Input", H5 A11 (in) "Address Input", H6 A20 (in) "Address Input"
part B pins: A1 NC "No Connection", B1 NC "No Connection", B2 NC "No Connection", C1 NC "No Connection", C2 NC "No Connection", D2 NC "No Connection", E2 NC "No Connection", E3 NC "No Connection", F1 NC "No Connection", F2 NC "No Connection", G1 NC "No Connection"

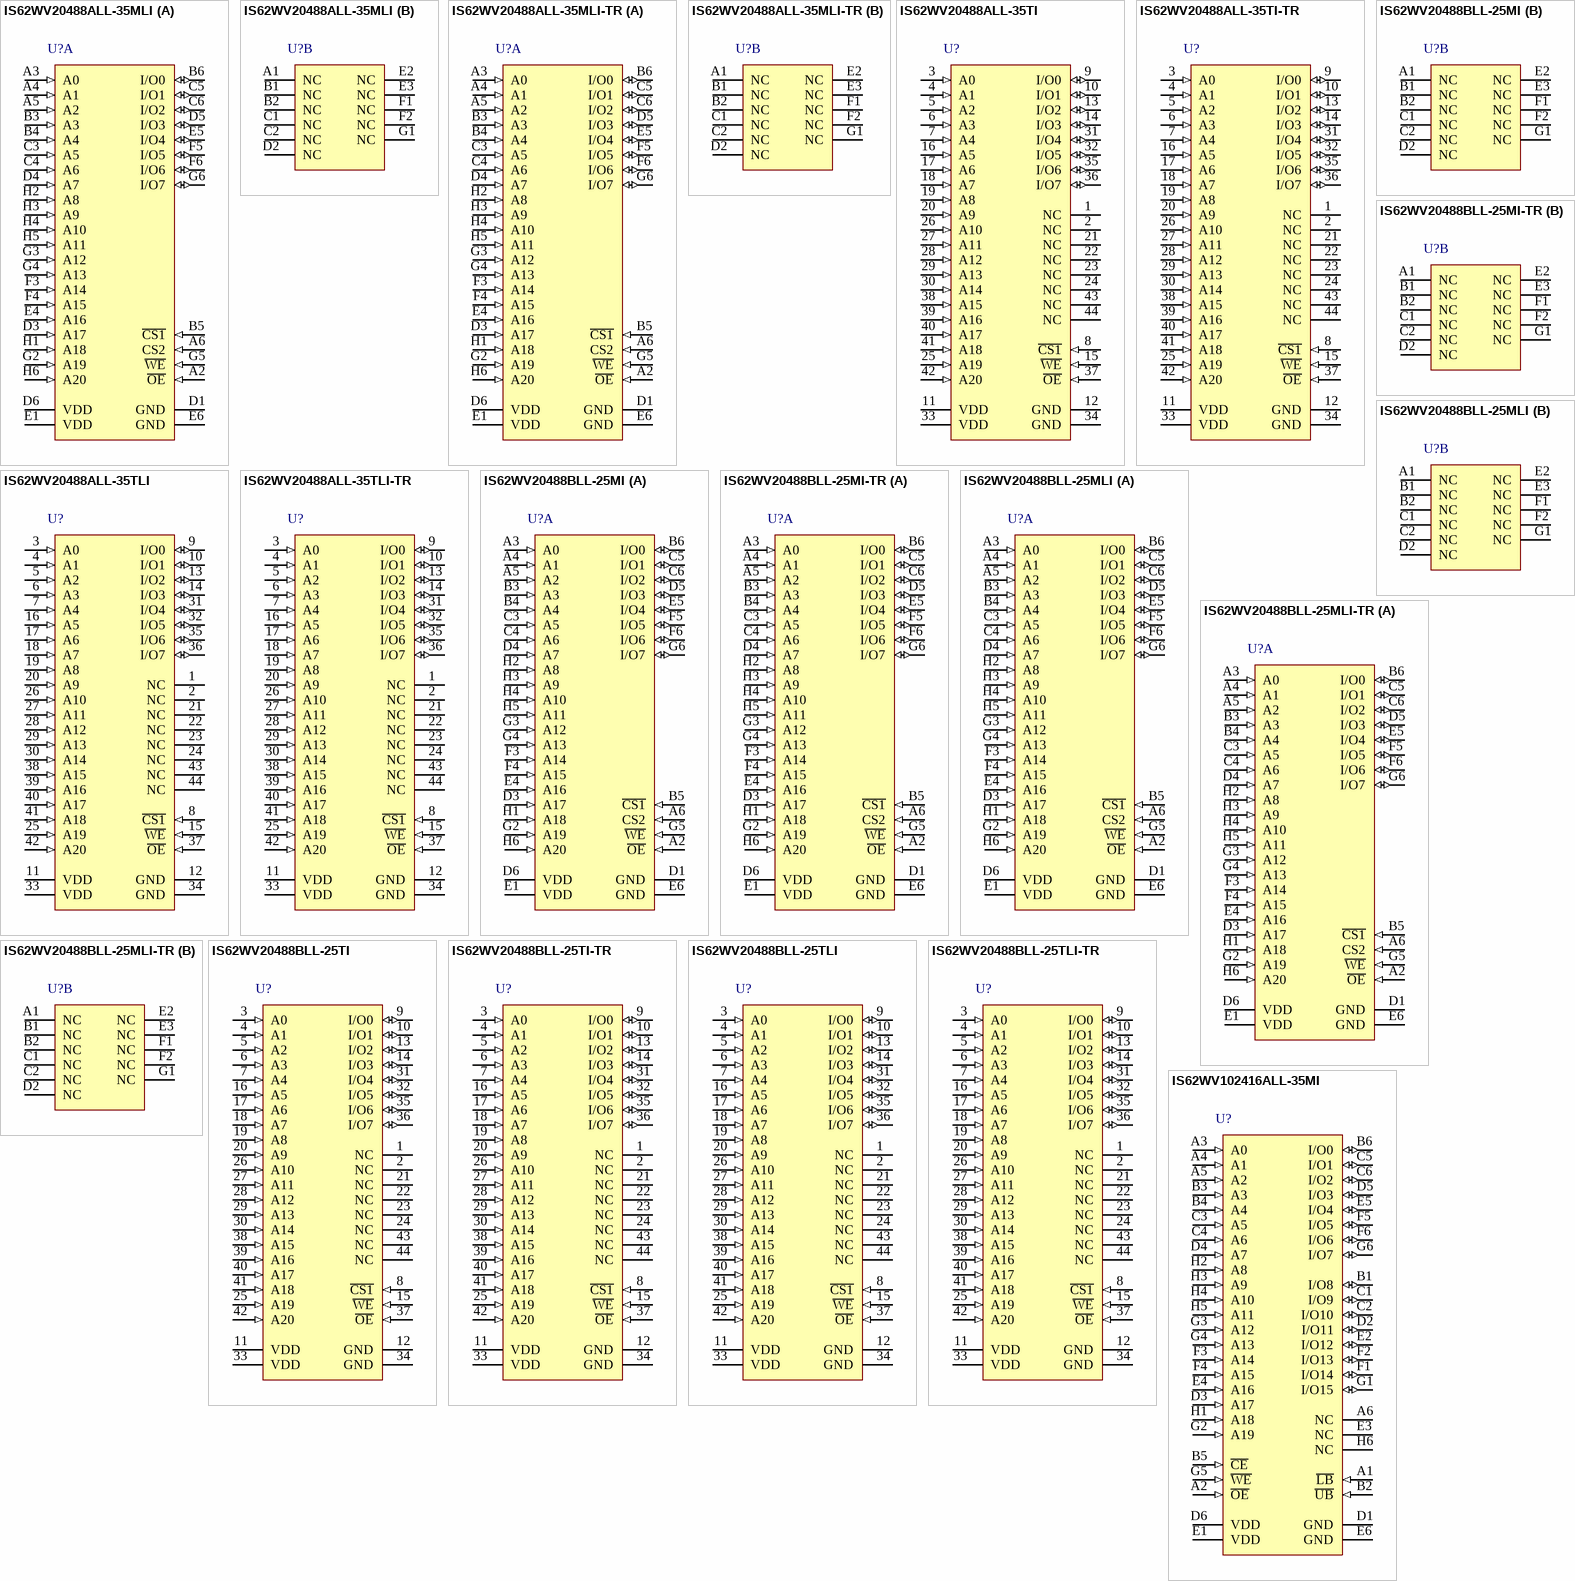
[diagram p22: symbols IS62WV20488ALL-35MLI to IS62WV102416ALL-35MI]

## IS62WV20488ALL-35MLI
designator U?
16 M High Speed Low Power CMOS SRAM, 2 M x 8, -40 to 85 degC, 48-Pin BGA (TF-BGA-48), Pb-Free; Manufacturer: Integrated Silicon Solution Inc (ISSI); PartNumber: IS62WV20488ALL-35MLI; Density: 16M; Organization: 2M x 8; Packing: Tray / Tube; Speed (ns): 35
footprint ISSI-TF-BGA-48-9000x11000DE (BGA, 48-Balls, Body 11x9mm, Pitch 0.75mm)
part A pins: A2 ~{OE} (in) "Output Enable Input", A3 A0 (in) "Address Input", A4 A1 (in) "Address Input", A5 A2 (in) "Address Input", A6 CS2 (in) "Chip Enable Input", B3 A3 (in) "Address Input", B4 A4 (in) "Address Input", B5 ~{CS1} (in) "Chip Enable Input", B6 I/O0 (io) "Data Input / Output", C3 A5 (in) "Address Input", C4 A6 (in) "Address Input", C5 I/O1 (io) "Data Input / Output", C6 I/O2 (io) "Data Input / Output", D1 GND (power) "Ground", D3 A17 (in) "Address Input", D4 A7 (in) "Address Input", D5 I/O3 (io) "Data Input / Output", D6 VDD (power) "Power", E1 VDD (power) "Power", E4 A16 (in) "Address Input", E5 I/O4 (io) "Data Input / Output", E6 GND (power) "Ground", F3 A14 (in) "Address Input", F4 A15 (in) "Address Input", F5 I/O5 (io) "Data Input / Output", F6 I/O6 (io) "Data Input / Output", G2 A19 (in) "Address Input", G3 A12 (in) "Address Input", G4 A13 (in) "Address Input", G5 ~{WE} (in) "Write Enable Input", G6 I/O7 (io) "Data Input / Output", H1 A18 (in) "Address Input", H2 A8 (in) "Address Input", H3 A9 (in) "Address Input", H4 A10 (in) "Address Input", H5 A11 (in) "Address Input", H6 A20 (in) "Address Input"
part B pins: A1 NC "No Connection", B1 NC "No Connection", B2 NC "No Connection", C1 NC "No Connection", C2 NC "No Connection", D2 NC "No Connection", E2 NC "No Connection", E3 NC "No Connection", F1 NC "No Connection", F2 NC "No Connection", G1 NC "No Connection"

## IS62WV20488ALL-35MLI-TR
designator U?
16 M High Speed Low Power CMOS SRAM, 2 M x 8, -40 to 85 degC, 48-Pin BGA (TF-BGA-48), Pb-Free; Manufacturer: Integrated Silicon Solution Inc (ISSI); PartNumber: IS62WV20488ALL-35MLI-TR; Density: 16M; Organization: 2M x 8; Packing: Tape & Reel; Speed (ns): 35
footprint ISSI-TF-BGA-48-9000x11000DE (BGA, 48-Balls, Body 11x9mm, Pitch 0.75mm)
part A pins: A2 ~{OE} (in) "Output Enable Input", A3 A0 (in) "Address Input", A4 A1 (in) "Address Input", A5 A2 (in) "Address Input", A6 CS2 (in) "Chip Enable Input", B3 A3 (in) "Address Input", B4 A4 (in) "Address Input", B5 ~{CS1} (in) "Chip Enable Input", B6 I/O0 (io) "Data Input / Output", C3 A5 (in) "Address Input", C4 A6 (in) "Address Input", C5 I/O1 (io) "Data Input / Output", C6 I/O2 (io) "Data Input / Output", D1 GND (power) "Ground", D3 A17 (in) "Address Input", D4 A7 (in) "Address Input", D5 I/O3 (io) "Data Input / Output", D6 VDD (power) "Power", E1 VDD (power) "Power", E4 A16 (in) "Address Input", E5 I/O4 (io) "Data Input / Output", E6 GND (power) "Ground", F3 A14 (in) "Address Input", F4 A15 (in) "Address Input", F5 I/O5 (io) "Data Input / Output", F6 I/O6 (io) "Data Input / Output", G2 A19 (in) "Address Input", G3 A12 (in) "Address Input", G4 A13 (in) "Address Input", G5 ~{WE} (in) "Write Enable Input", G6 I/O7 (io) "Data Input / Output", H1 A18 (in) "Address Input", H2 A8 (in) "Address Input", H3 A9 (in) "Address Input", H4 A10 (in) "Address Input", H5 A11 (in) "Address Input", H6 A20 (in) "Address Input"
part B pins: A1 NC "No Connection", B1 NC "No Connection", B2 NC "No Connection", C1 NC "No Connection", C2 NC "No Connection", D2 NC "No Connection", E2 NC "No Connection", E3 NC "No Connection", F1 NC "No Connection", F2 NC "No Connection", G1 NC "No Connection"

## IS62WV20488ALL-35TI
designator U?
16 M High Speed Low Power CMOS SRAM, 2 M x 8, -40 to 85 degC, 44-Pin SOP (TSOP-2-44); Manufacturer: Integrated Silicon Solution Inc (ISSI); PartNumber: IS62WV20488ALL-35TI; Density: 16M; Organization: 2M x 8; Packing: Tray / Tube; Speed (ns): 35
footprint ISSI-TSOP-2-44_N (SOP, 44-Leads, Body 18.5x10.3mm, Pitch 0.8mm, IPC Medium Density)
pins: 1 NC "No Connection", 2 NC "No Connection", 3 A0 (in) "Address Inputs", 4 A1 (in) "Address Inputs", 5 A2 (in) "Address Inputs", 6 A3 (in) "Address Inputs", 7 A4 (in) "Address Inputs", 8 ~{CS1} (in) "Chip Enable Input", 9 I/O0 (io) "Data Input / Output", 10 I/O1 (io) "Data Input / Output", 11 VDD (power) "Power", 12 GND (power) "Ground", 13 I/O2 (io) "Data Input / Output", 14 I/O3 (io) "Data Input / Output", 15 ~{WE} (in) "Write Enable Input", 16 A5 (in) "Address Inputs", 17 A6 (in) "Address Inputs", 18 A7 (in) "Address Inputs", 19 A8 (in) "Address Inputs", 20 A9 (in) "Address Inputs", 21 NC "No Connection", 22 NC "No Connection", 23 NC "No Connection", 24 NC "No Connection", 25 A19 (in) "Address Inputs", 26 A10 (in) "Address Inputs", 27 A11 (in) "Address Inputs", 28 A12 (in) "Address Inputs", 29 A13 (in) "Address Inputs", 30 A14 (in) "Address Inputs", 31 I/O4 (io) "Data Input / Output", 32 I/O5 (io) "Data Input / Output", 33 VDD (power) "Power", 34 GND (power) "Ground", 35 I/O6 (io) "Data Input / Output", 36 I/O7 (io) "Data Input / Output", 37 ~{OE} (in) "Output Enable Input", 38 A15 (in) "Address Inputs", 39 A16 (in) "Address Inputs", 40 A17 (in) "Address Inputs", 41 A18 (in) "Address Inputs", 42 A20 (in) "Address Inputs", 43 NC "No Connection", 44 NC "No Connection"

## IS62WV20488ALL-35TI-TR
designator U?
16 M High Speed Low Power CMOS SRAM, 2 M x 8, -40 to 85 degC, 44-Pin SOP (TSOP-2-44); Manufacturer: Integrated Silicon Solution Inc (ISSI); PartNumber: IS62WV20488ALL-35TI-TR; Density: 16M; Organization: 2M x 8; Packing: Tape & Reel; Speed (ns): 35
footprint ISSI-TSOP-2-44_N (SOP, 44-Leads, Body 18.5x10.3mm, Pitch 0.8mm, IPC Medium Density)
pins: 1 NC "No Connection", 2 NC "No Connection", 3 A0 (in) "Address Inputs", 4 A1 (in) "Address Inputs", 5 A2 (in) "Address Inputs", 6 A3 (in) "Address Inputs", 7 A4 (in) "Address Inputs", 8 ~{CS1} (in) "Chip Enable Input", 9 I/O0 (io) "Data Input / Output", 10 I/O1 (io) "Data Input / Output", 11 VDD (power) "Power", 12 GND (power) "Ground", 13 I/O2 (io) "Data Input / Output", 14 I/O3 (io) "Data Input / Output", 15 ~{WE} (in) "Write Enable Input", 16 A5 (in) "Address Inputs", 17 A6 (in) "Address Inputs", 18 A7 (in) "Address Inputs", 19 A8 (in) "Address Inputs", 20 A9 (in) "Address Inputs", 21 NC "No Connection", 22 NC "No Connection", 23 NC "No Connection", 24 NC "No Connection", 25 A19 (in) "Address Inputs", 26 A10 (in) "Address Inputs", 27 A11 (in) "Address Inputs", 28 A12 (in) "Address Inputs", 29 A13 (in) "Address Inputs", 30 A14 (in) "Address Inputs", 31 I/O4 (io) "Data Input / Output", 32 I/O5 (io) "Data Input / Output", 33 VDD (power) "Power", 34 GND (power) "Ground", 35 I/O6 (io) "Data Input / Output", 36 I/O7 (io) "Data Input / Output", 37 ~{OE} (in) "Output Enable Input", 38 A15 (in) "Address Inputs", 39 A16 (in) "Address Inputs", 40 A17 (in) "Address Inputs", 41 A18 (in) "Address Inputs", 42 A20 (in) "Address Inputs", 43 NC "No Connection", 44 NC "No Connection"

## IS62WV20488ALL-35TLI
designator U?
16 M High Speed Low Power CMOS SRAM, 2 M x 8, -40 to 85 degC, 44-Pin SOP (TSOP-2-44), Pb-Free; Manufacturer: Integrated Silicon Solution Inc (ISSI); PartNumber: IS62WV20488ALL-35TLI; Density: 16M; Organization: 2M x 8; Packing: Tray / Tube; Speed (ns): 35
footprint ISSI-TSOP-2-44_N (SOP, 44-Leads, Body 18.5x10.3mm, Pitch 0.8mm, IPC Medium Density)
pins: 1 NC "No Connection", 2 NC "No Connection", 3 A0 (in) "Address Inputs", 4 A1 (in) "Address Inputs", 5 A2 (in) "Address Inputs", 6 A3 (in) "Address Inputs", 7 A4 (in) "Address Inputs", 8 ~{CS1} (in) "Chip Enable Input", 9 I/O0 (io) "Data Input / Output", 10 I/O1 (io) "Data Input / Output", 11 VDD (power) "Power", 12 GND (power) "Ground", 13 I/O2 (io) "Data Input / Output", 14 I/O3 (io) "Data Input / Output", 15 ~{WE} (in) "Write Enable Input", 16 A5 (in) "Address Inputs", 17 A6 (in) "Address Inputs", 18 A7 (in) "Address Inputs", 19 A8 (in) "Address Inputs", 20 A9 (in) "Address Inputs", 21 NC "No Connection", 22 NC "No Connection", 23 NC "No Connection", 24 NC "No Connection", 25 A19 (in) "Address Inputs", 26 A10 (in) "Address Inputs", 27 A11 (in) "Address Inputs", 28 A12 (in) "Address Inputs", 29 A13 (in) "Address Inputs", 30 A14 (in) "Address Inputs", 31 I/O4 (io) "Data Input / Output", 32 I/O5 (io) "Data Input / Output", 33 VDD (power) "Power", 34 GND (power) "Ground", 35 I/O6 (io) "Data Input / Output", 36 I/O7 (io) "Data Input / Output", 37 ~{OE} (in) "Output Enable Input", 38 A15 (in) "Address Inputs", 39 A16 (in) "Address Inputs", 40 A17 (in) "Address Inputs", 41 A18 (in) "Address Inputs", 42 A20 (in) "Address Inputs", 43 NC "No Connection", 44 NC "No Connection"

## IS62WV20488ALL-35TLI-TR
designator U?
16 M High Speed Low Power CMOS SRAM, 2 M x 8, -40 to 85 degC, 44-Pin SOP (TSOP-2-44), Pb-Free; Manufacturer: Integrated Silicon Solution Inc (ISSI); PartNumber: IS62WV20488ALL-35TLI-TR; Density: 16M; Organization: 2M x 8; Packing: Tape & Reel; Speed (ns): 35
footprint ISSI-TSOP-2-44_N (SOP, 44-Leads, Body 18.5x10.3mm, Pitch 0.8mm, IPC Medium Density)
pins: 1 NC "No Connection", 2 NC "No Connection", 3 A0 (in) "Address Inputs", 4 A1 (in) "Address Inputs", 5 A2 (in) "Address Inputs", 6 A3 (in) "Address Inputs", 7 A4 (in) "Address Inputs", 8 ~{CS1} (in) "Chip Enable Input", 9 I/O0 (io) "Data Input / Output", 10 I/O1 (io) "Data Input / Output", 11 VDD (power) "Power", 12 GND (power) "Ground", 13 I/O2 (io) "Data Input / Output", 14 I/O3 (io) "Data Input / Output", 15 ~{WE} (in) "Write Enable Input", 16 A5 (in) "Address Inputs", 17 A6 (in) "Address Inputs", 18 A7 (in) "Address Inputs", 19 A8 (in) "Address Inputs", 20 A9 (in) "Address Inputs", 21 NC "No Connection", 22 NC "No Connection", 23 NC "No Connection", 24 NC "No Connection", 25 A19 (in) "Address Inputs", 26 A10 (in) "Address Inputs", 27 A11 (in) "Address Inputs", 28 A12 (in) "Address Inputs", 29 A13 (in) "Address Inputs", 30 A14 (in) "Address Inputs", 31 I/O4 (io) "Data Input / Output", 32 I/O5 (io) "Data Input / Output", 33 VDD (power) "Power", 34 GND (power) "Ground", 35 I/O6 (io) "Data Input / Output", 36 I/O7 (io) "Data Input / Output", 37 ~{OE} (in) "Output Enable Input", 38 A15 (in) "Address Inputs", 39 A16 (in) "Address Inputs", 40 A17 (in) "Address Inputs", 41 A18 (in) "Address Inputs", 42 A20 (in) "Address Inputs", 43 NC "No Connection", 44 NC "No Connection"

## IS62WV20488BLL-25MI
designator U?
16 M High Speed Low Power CMOS SRAM, 2 M x 8, -40 to 85 degC, 48-Pin BGA (TF-BGA-48); Manufacturer: Integrated Silicon Solution Inc (ISSI); PartNumber: IS62WV20488BLL-25MI; Density: 16M; Organization: 2M x 8; Packing: Tray / Tube; Speed (ns): 25
footprint ISSI-TF-BGA-48-9000x11000DE (BGA, 48-Balls, Body 11x9mm, Pitch 0.75mm)
part A pins: A2 ~{OE} (in) "Output Enable Input", A3 A0 (in) "Address Input", A4 A1 (in) "Address Input", A5 A2 (in) "Address Input", A6 CS2 (in) "Chip Enable Input", B3 A3 (in) "Address Input", B4 A4 (in) "Address Input", B5 ~{CS1} (in) "Chip Enable Input", B6 I/O0 (io) "Data Input / Output", C3 A5 (in) "Address Input", C4 A6 (in) "Address Input", C5 I/O1 (io) "Data Input / Output", C6 I/O2 (io) "Data Input / Output", D1 GND (power) "Ground", D3 A17 (in) "Address Input", D4 A7 (in) "Address Input", D5 I/O3 (io) "Data Input / Output", D6 VDD (power) "Power", E1 VDD (power) "Power", E4 A16 (in) "Address Input", E5 I/O4 (io) "Data Input / Output", E6 GND (power) "Ground", F3 A14 (in) "Address Input", F4 A15 (in) "Address Input", F5 I/O5 (io) "Data Input / Output", F6 I/O6 (io) "Data Input / Output", G2 A19 (in) "Address Input", G3 A12 (in) "Address Input", G4 A13 (in) "Address Input", G5 ~{WE} (in) "Write Enable Input", G6 I/O7 (io) "Data Input / Output", H1 A18 (in) "Address Input", H2 A8 (in) "Address Input", H3 A9 (in) "Address Input", H4 A10 (in) "Address Input", H5 A11 (in) "Address Input", H6 A20 (in) "Address Input"
part B pins: A1 NC "No Connection", B1 NC "No Connection", B2 NC "No Connection", C1 NC "No Connection", C2 NC "No Connection", D2 NC "No Connection", E2 NC "No Connection", E3 NC "No Connection", F1 NC "No Connection", F2 NC "No Connection", G1 NC "No Connection"

## IS62WV20488BLL-25MI-TR
designator U?
16 M High Speed Low Power CMOS SRAM, 2 M x 8, -40 to 85 degC, 48-Pin BGA (TF-BGA-48); Manufacturer: Integrated Silicon Solution Inc (ISSI); PartNumber: IS62WV20488BLL-25MI-TR; Density: 16M; Organization: 2M x 8; Packing: Tape & Reel; Speed (ns): 25
footprint ISSI-TF-BGA-48-9000x11000DE (BGA, 48-Balls, Body 11x9mm, Pitch 0.75mm)
part A pins: A2 ~{OE} (in) "Output Enable Input", A3 A0 (in) "Address Input", A4 A1 (in) "Address Input", A5 A2 (in) "Address Input", A6 CS2 (in) "Chip Enable Input", B3 A3 (in) "Address Input", B4 A4 (in) "Address Input", B5 ~{CS1} (in) "Chip Enable Input", B6 I/O0 (io) "Data Input / Output", C3 A5 (in) "Address Input", C4 A6 (in) "Address Input", C5 I/O1 (io) "Data Input / Output", C6 I/O2 (io) "Data Input / Output", D1 GND (power) "Ground", D3 A17 (in) "Address Input", D4 A7 (in) "Address Input", D5 I/O3 (io) "Data Input / Output", D6 VDD (power) "Power", E1 VDD (power) "Power", E4 A16 (in) "Address Input", E5 I/O4 (io) "Data Input / Output", E6 GND (power) "Ground", F3 A14 (in) "Address Input", F4 A15 (in) "Address Input", F5 I/O5 (io) "Data Input / Output", F6 I/O6 (io) "Data Input / Output", G2 A19 (in) "Address Input", G3 A12 (in) "Address Input", G4 A13 (in) "Address Input", G5 ~{WE} (in) "Write Enable Input", G6 I/O7 (io) "Data Input / Output", H1 A18 (in) "Address Input", H2 A8 (in) "Address Input", H3 A9 (in) "Address Input", H4 A10 (in) "Address Input", H5 A11 (in) "Address Input", H6 A20 (in) "Address Input"
part B pins: A1 NC "No Connection", B1 NC "No Connection", B2 NC "No Connection", C1 NC "No Connection", C2 NC "No Connection", D2 NC "No Connection", E2 NC "No Connection", E3 NC "No Connection", F1 NC "No Connection", F2 NC "No Connection", G1 NC "No Connection"

## IS62WV20488BLL-25MLI
designator U?
16 M High Speed Low Power CMOS SRAM, 2 M x 8, -40 to 85 degC, 48-Pin BGA (TF-BGA-48), Pb-Free; Manufacturer: Integrated Silicon Solution Inc (ISSI); PartNumber: IS62WV20488BLL-25MLI; Density: 16M; Organization: 2M x 8; Packing: Tray / Tube; Speed (ns): 25
footprint ISSI-TF-BGA-48-9000x11000DE (BGA, 48-Balls, Body 11x9mm, Pitch 0.75mm)
part A pins: A2 ~{OE} (in) "Output Enable Input", A3 A0 (in) "Address Input", A4 A1 (in) "Address Input", A5 A2 (in) "Address Input", A6 CS2 (in) "Chip Enable Input", B3 A3 (in) "Address Input", B4 A4 (in) "Address Input", B5 ~{CS1} (in) "Chip Enable Input", B6 I/O0 (io) "Data Input / Output", C3 A5 (in) "Address Input", C4 A6 (in) "Address Input", C5 I/O1 (io) "Data Input / Output", C6 I/O2 (io) "Data Input / Output", D1 GND (power) "Ground", D3 A17 (in) "Address Input", D4 A7 (in) "Address Input", D5 I/O3 (io) "Data Input / Output", D6 VDD (power) "Power", E1 VDD (power) "Power", E4 A16 (in) "Address Input", E5 I/O4 (io) "Data Input / Output", E6 GND (power) "Ground", F3 A14 (in) "Address Input", F4 A15 (in) "Address Input", F5 I/O5 (io) "Data Input / Output", F6 I/O6 (io) "Data Input / Output", G2 A19 (in) "Address Input", G3 A12 (in) "Address Input", G4 A13 (in) "Address Input", G5 ~{WE} (in) "Write Enable Input", G6 I/O7 (io) "Data Input / Output", H1 A18 (in) "Address Input", H2 A8 (in) "Address Input", H3 A9 (in) "Address Input", H4 A10 (in) "Address Input", H5 A11 (in) "Address Input", H6 A20 (in) "Address Input"
part B pins: A1 NC "No Connection", B1 NC "No Connection", B2 NC "No Connection", C1 NC "No Connection", C2 NC "No Connection", D2 NC "No Connection", E2 NC "No Connection", E3 NC "No Connection", F1 NC "No Connection", F2 NC "No Connection", G1 NC "No Connection"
